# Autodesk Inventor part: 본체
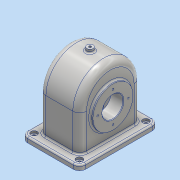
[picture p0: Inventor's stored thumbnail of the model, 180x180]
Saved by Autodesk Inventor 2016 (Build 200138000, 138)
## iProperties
Created: 2018-11
Part Number: 본체
Material: 알루미늄 6061
Document SubType Name: Modeling
Designer: user
Mass: 1092.08 g
Surface Area: 1182.21 cm^2
Volume: 404.475 cm^3
Density: 2.7 g/cm^3
Appearance: 알루미늄 - 평지
Author: user
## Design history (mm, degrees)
sketch "스케치1"
  geometry: L1 (-55, -75)-(55, -75); L2 (55, -75)-(55, 75); L3 (55, 75)-(-55, 75); L4 (-55, 75)-(-55, -75); L5 (-55, -75)-(55, 75); L6 (55, -75)-(-55, 75); 1 further point
  constraints: 12 end point, 2 midpoint, 2 parallel, 1 horizontal, 1 perpendicular
  dimensions: "d0" = 110 distance of L3.end L2.end; "d1" = 150 distance of L2.end L1.end
extrude "돌출1" new body sketch "스케치1" distance "d2" = 10; taper "d3" = 0 deg
sketch "스케치2"
  geometry: L1 (38.5, 58)-(-38.5, 58); L2 (-38.5, 58)-(-38.5, -58); L3 (-38.5, -58)-(38.5, -58); L4 (38.5, -58)-(38.5, 58); L5 (38.5, 58)-(-38.5, -58); L6 (-38.5, 58)-(38.5, -58); 1 further point
  constraints: 12 end point, 2 midpoint, 2 parallel, 1 horizontal, 1 perpendicular
  dimensions: "d4" = 77 distance of L3.end L2.end; "d5" = 116 distance of L1.end L2.end
extrude "돌출2" join sketch "스케치2" distance "d6" = 126; taper "d7" = 0 deg
fillet "모깎기1" dims "d8" = 58
feature "쉘1" dims "d10" = 10, "d11" = 5, "d27" = 6
node "작업 평면1"
sketch "스케치3"
  geometry: C1 r 6 at (0, 0); 1 further point
  constraints: 1 centre point, 1 coincident
  dimensions: "d13" = 12 diameter of C1
extrude "돌출3" join sketch "스케치3" stored distance "d14" = 126; taper "d15" = 5 deg
sketch "스케치7"
  geometry: L1 (10, -17)-(10, 133) reference; C1 r 38 at (-55, 58); 2 further points
  constraints: 1 centre point, 1 horizontal alignment, 1 midpoint
  dimensions: "d28" = 76 diameter of C1; "d29" = 65 distance from line of L1 C1.centre
extrude "돌출7" join sketch "스케치7" distance "d30" = 5; taper "d31" = 0 deg
sketch "스케치8"
  geometry: L1 (-10, 133)-(-10, -17) reference; C1 r 38 at (55, 58); 2 further points
  constraints: 1 centre point, 1 horizontal alignment, 1 midpoint
  dimensions: "d32" = 76 diameter of C1; "d33" = 65 distance from line of L1 C1.centre
extrude "돌출8" join sketch "스케치8" distance "d34" = 10; taper "d35" = 0 deg
node "작업 평면2"
sketch "스케치10"
  geometry: C1 r 28 at (0, 0); 1 further point
  constraints: 1 centre point, 1 vertical alignment
  dimensions: "d40" = 56 diameter of C1; "d41" = 65 distance of point (0, -65) C1.centre
extrude "돌출10" join sketch "스케치10" distance "d42" = 14; taper "d43" = 40 deg
sketch "스케치9"
  geometry: C1 r 20 at (0, 0); C2 r 38 at (0, 0) reference; 1 further point
  constraints: 1 centre point, 1 concentric
  dimensions: "d36" = 40 diameter of C1
extrude "돌출9" cut sketch "스케치9" stored distance "d37" = 10; taper "d38" = 0 deg
sketch "스케치11"
  geometry: L1 (65, -75)-(65, 75) reference; C1 r 20 at (0, 0) reference; 3 further points
  constraints: 1 horizontal alignment, 1 midpoint
  dimensions: "d44" = 29 distance of C1.centre point (-29, 0)
hole "구멍1" sketch "스케치11" at (-29, 0) diameter "d45" = 3.242; stored, may be unused: countersink angle "d49" = 90 deg, drill point angle "d51" = 118 deg; dims "d46" = 8, "d47" = 4, "d48" = 2, "d50" = 10
sketch "스케치12"
  geometry: L1 (-65, 75)-(-65, -75) reference; C1 r 20 at (0, 0) reference; 3 further points
  constraints: 1 horizontal alignment, 1 midpoint
  dimensions: "d55" = 29 distance of C1.centre point (29, 0)
hole "구멍2" sketch "스케치12" at (29, 0) diameter "d56" = 3.242; stored, may be unused: countersink angle "d60" = 90 deg, drill point angle "d62" = 118 deg; dims "d57" = 8, "d58" = 4, "d59" = 2, "d61" = 10
sketch "스케치13"
  geometry: 2 further points
  constraints: 1 coincident
hole "구멍3" sketch "스케치13" at (0, 0) diameter "d66" = 4.459; stored, may be unused: countersink angle "d70" = 90 deg, drill point angle "d72" = 118 deg; dims "d67" = 30, "d68" = 4, "d69" = 2, "d71" = 34.95
fillet "모깎기3" dims "d73" = 12
fillet "모깎기4" dims "d74" = 3
sketch "스케치14"
  geometry: A1 r 12 centre (43, -63) between (43, -75) and (55, -63) reference; A2 r 9 centre (-43, -63) between (-52, -63) and (-43, -72) reference; A3 r 12 centre (-43, 63) between (-43, 75) and (-55, 63) reference; A4 r 12 centre (43, 63) between (55, 63) and (43, 75) reference; 5 further points
  constraints: 4 coincident
hole "구멍4" sketch "스케치14" at (43, -63), (-43, -63), (-43, 63), (43, 63) diameter "d75" = 5; stored, may be unused: countersink angle "d79" = 90 deg, drill point angle "d81" = 118 deg; dims "d76" = 30, "d77" = 12, "d78" = 4, "d80" = 34.95
fillet "모깎기5" dims "d82" = 13
fillet "모깎기6" dims "d83" = 3
chamfer "모따기1" distance "d84" = 1; stored, may be unused: second distance "d85" = 2, angle "d86" = 45 deg
fillet "모깎기7" dims "d87" = 8
fillet "모깎기8" dims "d88" = 3
sketch "스케치15"
  geometry: L1 (68.5, 78)-(-17.5, 78) reference; 3 further points
  constraints: 1 midpoint, 1 vertical alignment, 1 other
  dimensions: "d89" = 40 distance from line of L1 point (25.5, 38)
feature "엠보싱1" sketch "스케치15" dims "d0" = 110, "d1" = 150, "d90" = 0.5, "d91" = 0
node "솔리드1"
pattern_circular "원형 패턴1" dims angle "d53" = 360 deg
pattern_circular "원형 패턴2" dims angle "d64" = 360 deg
other parameters: "d12" = 142, "d39" = -24
